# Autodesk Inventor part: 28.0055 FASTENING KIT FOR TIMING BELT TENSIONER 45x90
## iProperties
Created: 2007-06
Part Number: 28.0055 FASTENING KIT FOR TIMING BELT TENSIONER 45x90
Document SubType Name: Modeling
Designer: Andy Moles
Material: Aluminum-6061
Density: 2.71 g/cm^3
Author: Andy Moles
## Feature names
1. Extrusion1
2. Hole1
